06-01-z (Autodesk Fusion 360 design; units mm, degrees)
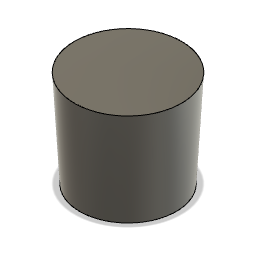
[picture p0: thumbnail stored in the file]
sketch "スケッチ" plane through (0, 0, 0) normal (0, 0, 1) x axis (1, 0, 0)
  line L1 (0, 45) -> (0, 0)
  line L2 (-25, 45) -> (0, 45)
  line L3 (-22.5, 0) -> (-25, 45)
  line L4 (0, 0) -> (-22.5, 0)
  point P1 (0, 0)
  point P2 (0, 0)
  point P3 (0, 45)
  point P5 (-22.5, 0)
  coincident P1 P2
  vertical L1
  perpendicular L1 L2
  perpendicular L1 L4
  dimension "d1" = 50
  dimension "d2" distance P2 P3 = 45
  dimension "d3" distance L1 P5 = 45
revolve "回転" sketch "スケッチ" AlongAngle 360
